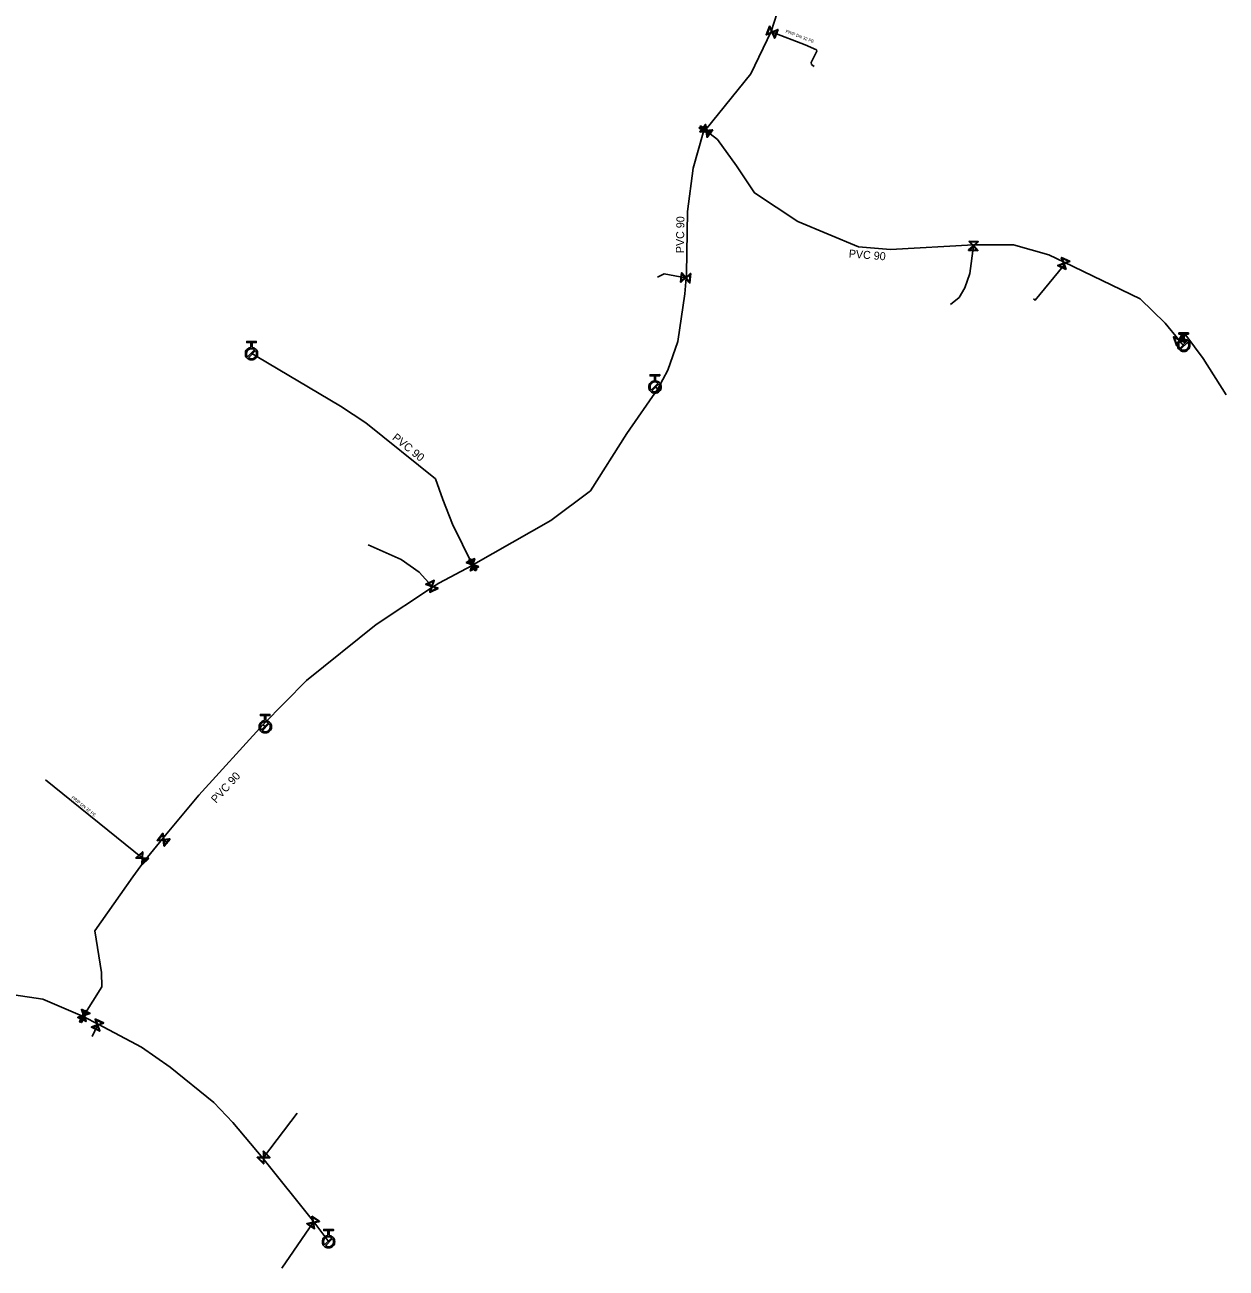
# Model space of a CAD drawing. Extents: x -641905 to -641246, y -1111750 to -1110210.
# Drawn here: x -641516.8 to -641321.7, y -1110794 to -1110592 of the extents above; entities that cross this region are included whole.
import ezdxf

# ---------------------------------------------------------------- set-up
doc = ezdxf.new("R2010")
doc.units = 0
for name, color, linetype in [('Default', 7, 'Continuous'), ('VP Hydrant', 7, 'Continuous'), ('VP Popis přípojky', 7, 'Continuous'), ('VP Přípojka', 7, 'Continuous'), ('VP Řad', 7, 'Continuous'), ('VP Řad - popis', 7, 'Continuous'), ('VP Šoupě', 7, 'Continuous')]:
    doc.layers.add(name, color=color, linetype=linetype)

msp = doc.modelspace()

# ---------------------------------------------------------------- linework, layer by layer
at = {"layer": 'Default'}
for points in [[(-641479.89, -1110644.41), (-641479.53, -1110644.44), (-641479.27, -1110644.7), (-641478.98, -1110645), (-641478.98, -1110645.41), (-641478.98, -1110645.83), (-641479.27, -1110646.12), (-641479.57, -1110646.41), (-641479.98, -1110646.41), (-641480.4, -1110646.41), (-641480.69, -1110646.12), (-641480.98, -1110645.82), (-641480.98, -1110645.41), (-641480.98, -1110644.99), (-641480.69, -1110644.7), (-641480.43, -1110644.44), (-641480.07, -1110644.41)], [(-641328.51, -1110643.03), (-641328.15, -1110643.06), (-641327.89, -1110643.32), (-641327.6, -1110643.61), (-641327.6, -1110644.03), (-641327.6, -1110644.44), (-641327.89, -1110644.74), (-641328.18, -1110645.03), (-641328.6, -1110645.03), (-641329.01, -1110645.03), (-641329.3, -1110644.74), (-641329.6, -1110644.45), (-641329.6, -1110644.04), (-641329.6, -1110643.62), (-641329.31, -1110643.33), (-641329.05, -1110643.06), (-641328.7, -1110643.03)], [(-641328.09, -1110643.39), (-641328.31, -1110643.21), (-641328.6, -1110643.22), (-641328.94, -1110643.22), (-641329.18, -1110643.46), (-641329.42, -1110643.69), (-641329.41, -1110644.03), (-641329.41, -1110644.32), (-641329.23, -1110644.54)], [(-641329.11, -1110644.67), (-641328.89, -1110644.84), (-641328.6, -1110644.84), (-641328.26, -1110644.84), (-641328.03, -1110644.6), (-641327.79, -1110644.36), (-641327.79, -1110644.03), (-641327.79, -1110643.74), (-641327.96, -1110643.52)], [(-641479.47, -1110644.77), (-641479.69, -1110644.6), (-641479.98, -1110644.6), (-641480.32, -1110644.6), (-641480.56, -1110644.83), (-641480.79, -1110645.07), (-641480.79, -1110645.41), (-641480.79, -1110645.7), (-641480.62, -1110645.92)], [(-641480.49, -1110646.05), (-641480.27, -1110646.22), (-641479.98, -1110646.22), (-641479.65, -1110646.22), (-641479.41, -1110645.98), (-641479.17, -1110645.75), (-641479.17, -1110645.41), (-641479.17, -1110645.12), (-641479.34, -1110644.9)], [(-641414.37, -1110649.81), (-641414.01, -1110649.84), (-641413.75, -1110650.09), (-641413.46, -1110650.39), (-641413.45, -1110650.8), (-641413.45, -1110651.22), (-641413.74, -1110651.51), (-641414.03, -1110651.8), (-641414.45, -1110651.81), (-641414.86, -1110651.81), (-641415.15, -1110651.52), (-641415.45, -1110651.23), (-641415.45, -1110650.82), (-641415.46, -1110650.4), (-641415.17, -1110650.11), (-641414.91, -1110649.84), (-641414.55, -1110649.81)], [(-641413.95, -1110650.17), (-641414.17, -1110649.99), (-641414.46, -1110649.99), (-641414.8, -1110649.99), (-641415.03, -1110650.23), (-641415.27, -1110650.47), (-641415.27, -1110650.81), (-641415.26, -1110651.1), (-641415.09, -1110651.32)], [(-641414.96, -1110651.45), (-641414.74, -1110651.62), (-641414.45, -1110651.62), (-641414.11, -1110651.61), (-641413.88, -1110651.38), (-641413.64, -1110651.14), (-641413.64, -1110650.8), (-641413.64, -1110650.51), (-641413.82, -1110650.29)], [(-641477.66, -1110705.01), (-641477.3, -1110705.04), (-641477.04, -1110705.3), (-641476.75, -1110705.59), (-641476.75, -1110706.01), (-641476.75, -1110706.42), (-641477.04, -1110706.71), (-641477.33, -1110707.01), (-641477.75, -1110707.01), (-641478.16, -1110707.01), (-641478.45, -1110706.72), (-641478.75, -1110706.43), (-641478.75, -1110706.02), (-641478.75, -1110705.6), (-641478.46, -1110705.31), (-641478.21, -1110705.04), (-641477.85, -1110705.01)], [(-641477.24, -1110705.37), (-641477.46, -1110705.19), (-641477.76, -1110705.2), (-641478.09, -1110705.2), (-641478.33, -1110705.44), (-641478.57, -1110705.67), (-641478.56, -1110706.01), (-641478.56, -1110706.3), (-641478.38, -1110706.52)], [(-641478.25, -1110706.65), (-641478.04, -1110706.82), (-641477.75, -1110706.82), (-641477.41, -1110706.82), (-641477.17, -1110706.58), (-641476.94, -1110706.34), (-641476.94, -1110706), (-641476.94, -1110705.71), (-641477.12, -1110705.5)], [(-641467.38, -1110788.67), (-641467.02, -1110788.7), (-641466.76, -1110788.96), (-641466.47, -1110789.26), (-641466.47, -1110789.67), (-641466.47, -1110790.09), (-641466.76, -1110790.38), (-641467.06, -1110790.67), (-641467.47, -1110790.67), (-641467.89, -1110790.67), (-641468.18, -1110790.38), (-641468.47, -1110790.08), (-641468.47, -1110789.67), (-641468.47, -1110789.25), (-641468.18, -1110788.96), (-641467.92, -1110788.7), (-641467.56, -1110788.67)], [(-641466.96, -1110789.03), (-641467.18, -1110788.86), (-641467.47, -1110788.86), (-641467.81, -1110788.86), (-641468.05, -1110789.09), (-641468.28, -1110789.33), (-641468.28, -1110789.67), (-641468.28, -1110789.96), (-641468.11, -1110790.18)], [(-641467.98, -1110790.31), (-641467.76, -1110790.48), (-641467.47, -1110790.48), (-641467.14, -1110790.48), (-641466.9, -1110790.24), (-641466.66, -1110790.01), (-641466.66, -1110789.67), (-641466.66, -1110789.38), (-641466.83, -1110789.16)]]:
    msp.add_open_spline(points, degree=3, dxfattribs=at)
at = {"layer": 'VP Hydrant'}
for points in [[(-641328.7, -1110643.03), (-641328.7, -1110642.21), (-641329.39, -1110642.22), (-641329.39, -1110642.03), (-641327.83, -1110642.03), (-641327.83, -1110642.21), (-641328.51, -1110642.21), (-641328.51, -1110643.03)], [(-641480.07, -1110644.41), (-641480.07, -1110643.59), (-641480.76, -1110643.59), (-641480.76, -1110643.41), (-641479.2, -1110643.41), (-641479.2, -1110643.6), (-641479.89, -1110643.59), (-641479.89, -1110644.41)], [(-641329.23, -1110644.54), (-641328.09, -1110643.39)], [(-641327.96, -1110643.52), (-641329.11, -1110644.67)], [(-641480.62, -1110645.92), (-641479.47, -1110644.77)], [(-641479.34, -1110644.9), (-641480.49, -1110646.05)], [(-641414.55, -1110649.81), (-641414.56, -1110648.99), (-641415.25, -1110649), (-641415.25, -1110648.81), (-641413.69, -1110648.8), (-641413.68, -1110648.98), (-641414.37, -1110648.99), (-641414.37, -1110649.81)], [(-641415.09, -1110651.32), (-641413.95, -1110650.17)], [(-641413.82, -1110650.29), (-641414.96, -1110651.45)], [(-641477.85, -1110705.01), (-641477.85, -1110704.19), (-641478.54, -1110704.2), (-641478.54, -1110704.01), (-641476.98, -1110704.01), (-641476.98, -1110704.19), (-641477.67, -1110704.19), (-641477.66, -1110705.01)], [(-641478.38, -1110706.52), (-641477.24, -1110705.37)], [(-641477.12, -1110705.5), (-641478.25, -1110706.65)], [(-641467.56, -1110788.67), (-641467.56, -1110787.85), (-641468.25, -1110787.85), (-641468.25, -1110787.67), (-641466.68, -1110787.67), (-641466.68, -1110787.86), (-641467.37, -1110787.85), (-641467.38, -1110788.67)], [(-641468.11, -1110790.18), (-641466.96, -1110789.03)], [(-641466.83, -1110789.16), (-641467.98, -1110790.31)]]:
    msp.add_lwpolyline(points, dxfattribs=at)
at = {"layer": 'VP Přípojka'}
for points in [[(-641395.57, -1110593.08), (-641395.44, -1110593.17), (-641390.05, -1110595.24), (-641388.26, -1110596.06), (-641388.18, -1110596.27), (-641389.1, -1110598.1), (-641389.05, -1110598.41), (-641388.63, -1110598.73)], [(-641362.75, -1110627.69), (-641362.76, -1110627.9), (-641363.32, -1110632.37), (-641364.13, -1110634.68), (-641365.05, -1110636.27), (-641366.49, -1110637.4)], [(-641348, -1110630.55), (-641348.09, -1110630.75), (-641348.19, -1110631.16), (-641352.74, -1110636.71), (-641352.98, -1110636.48)], [(-641409.38, -1110633.09), (-641409.48, -1110633.08), (-641412.98, -1110632.43), (-641414.06, -1110632.98)], [(-641329.42, -1110643.17), (-641329.31, -1110643.13), (-641328.24, -1110642.4), (-641325.44, -1110646.17), (-641321.72, -1110652.11)], [(-641329.42, -1110643.17), (-641328.93, -1110643.78), (-641328.6, -1110644.03)], [(-641479.14, -1110645.84), (-641479.19, -1110645.93), (-641479.75, -1110646.36)], [(-641479.3, -1110645.75), (-641479.26, -1110645.69)], [(-641414.01, -1110651.09), (-641414.2, -1110650.97), (-641414.46, -1110650.8)], [(-641450.6, -1110683.34), (-641450.68, -1110683.18), (-641452.75, -1110680.91), (-641455.69, -1110678.84), (-641461.01, -1110676.46)], [(-641478.07, -1110705.66), (-641477.92, -1110705.86), (-641477.75, -1110706.01)], [(-641497.33, -1110727.77), (-641497.7, -1110727.36), (-641513.43, -1110714.64)], [(-641494.45, -1110724.21), (-641493.57, -1110724.89)], [(-641504.9, -1110754.3), (-641504.98, -1110754.47), (-641505.87, -1110756.34)], [(-641478.12, -1110776.08), (-641478.01, -1110775.97), (-641472.56, -1110768.8)], [(-641475.05, -1110793.95), (-641469.97, -1110786.54), (-641469.86, -1110786.42)], [(-641467.56, -1110789.47), (-641467.47, -1110789.67)]]:
    msp.add_lwpolyline(points, dxfattribs=at)
at = {"layer": 'VP Řad'}
for points in [[(-641406.62, -1110609.5), (-641406.42, -1110609.23), (-641406.35, -1110609.14), (-641406.3, -1110609.07), (-641406.23, -1110608.97), (-641398.89, -1110599.95), (-641395.57, -1110593.08), (-641393.64, -1110586.94), (-641393.63, -1110586.92), (-641392.58, -1110582.16), (-641391.51, -1110573.9), (-641391.83, -1110571.17), (-641393.23, -1110561.05), (-641393.28, -1110556.19), (-641394.73, -1110550.07), (-641395.83, -1110545.45), (-641395.85, -1110545.41), (-641395.9, -1110545.32), (-641397.5, -1110542.1), (-641404.8, -1110534.12), (-641410.42, -1110529.73), (-641417.1, -1110526.46)], [(-641444.03, -1110679.73), (-641443.93, -1110679.67), (-641431.4, -1110672.52), (-641424.94, -1110667.67), (-641419.04, -1110658.36), (-641414.01, -1110651.09), (-641412.35, -1110648.05), (-641410.74, -1110643.43), (-641409.63, -1110635.65), (-641409.38, -1110633.09), (-641409.32, -1110632.45), (-641409.16, -1110622.32), (-641408.25, -1110615.26), (-641406.62, -1110609.5)], [(-641406.3, -1110609.07), (-641406.23, -1110609.15), (-641404.29, -1110610.63), (-641401.21, -1110614.86), (-641398.29, -1110619.27), (-641391.25, -1110623.94), (-641381.4, -1110628.05), (-641376.23, -1110628.47), (-641362.75, -1110627.69), (-641356.26, -1110627.74), (-641350.48, -1110629.35), (-641348, -1110630.55), (-641335.7, -1110636.49), (-641331.6, -1110640.43), (-641329.42, -1110643.17)], [(-641479.14, -1110645.84), (-641479.3, -1110645.75), (-641479.63, -1110645.55), (-641479.98, -1110645.41)], [(-641444.03, -1110679.73), (-641444.09, -1110679.68), (-641444.09, -1110679.68), (-641447.35, -1110673.1), (-641448.91, -1110669.07), (-641450.11, -1110665.73), (-641461.39, -1110656.64), (-641465.55, -1110653.94), (-641479.14, -1110645.84)], [(-641507.31, -1110753.07), (-641507.2, -1110752.9), (-641504.29, -1110748.23), (-641504.36, -1110745.91), (-641505.4, -1110739.15), (-641499.25, -1110730.39), (-641498.4, -1110729.18), (-641497.33, -1110727.77), (-641494.45, -1110724.21), (-641493.95, -1110723.59), (-641488.51, -1110717.1), (-641478.07, -1110705.66), (-641471.04, -1110698.49), (-641459.74, -1110689.42), (-641450.6, -1110683.34), (-641449.55, -1110682.68), (-641444.16, -1110679.81), (-641444.03, -1110679.73)], [(-641624.02, -1110725.37), (-641622.04, -1110726.09), (-641605.04, -1110732.39), (-641592.38, -1110736.75), (-641580.95, -1110740.68), (-641580.55, -1110740.8), (-641577.05, -1110741.87), (-641571.34, -1110743.62), (-641560.51, -1110747.22), (-641550.89, -1110749.28), (-641542.88, -1110749.95), (-641530.96, -1110748.44), (-641525.88, -1110748.46), (-641513.84, -1110750.25), (-641507.42, -1110753.04), (-641507.31, -1110753.07)], [(-641507.31, -1110753.07), (-641507.19, -1110753.15), (-641504.9, -1110754.3), (-641497.86, -1110758.07), (-641493.16, -1110761.28), (-641486.08, -1110767.06), (-641483, -1110770.28), (-641478.12, -1110776.08), (-641469.86, -1110786.42), (-641467.56, -1110789.47)]]:
    msp.add_lwpolyline(points, dxfattribs=at)
at = {"layer": 'VP Šoupě'}
for points in [[(-641394.47, -1110592.75), (-641395.02, -1110594.14), (-641395.08, -1110594.12), (-641395.13, -1110594), (-641395.46, -1110593.23), (-641396.35, -1110593.61), (-641396.41, -1110593.59), (-641395.86, -1110592.2), (-641395.8, -1110592.22), (-641395.42, -1110593.11), (-641394.64, -1110592.78), (-641394.53, -1110592.73), (-641394.47, -1110592.75)], [(-641396.27, -1110593.48), (-641395.5, -1110593.15), (-641395.83, -1110592.38), (-641396.27, -1110593.48)], [(-641394.61, -1110592.86), (-641395.38, -1110593.19), (-641395.05, -1110593.96), (-641394.61, -1110592.86)], [(-641405.6, -1110609.81), (-641407.3, -1110608.75), (-641407.23, -1110608.64), (-641405.53, -1110609.7), (-641405.6, -1110609.81)], [(-641405.07, -1110609.06), (-641405.98, -1110610.26), (-641406.04, -1110610.22), (-641406.05, -1110610.09), (-641406.16, -1110609.26), (-641407.12, -1110609.39), (-641407.18, -1110609.35), (-641406.27, -1110608.15), (-641406.21, -1110608.19), (-641406.09, -1110609.16), (-641405.25, -1110609.04), (-641405.13, -1110609.02), (-641405.07, -1110609.06)], [(-641405.41, -1110609.54), (-641407.12, -1110608.51), (-641407.05, -1110608.4), (-641405.34, -1110609.43), (-641405.41, -1110609.54)], [(-641407.01, -1110609.28), (-641406.17, -1110609.17), (-641406.29, -1110608.33), (-641407.01, -1110609.28)], [(-641405.24, -1110609.13), (-641406.07, -1110609.24), (-641405.96, -1110610.07), (-641405.24, -1110609.13)], [(-641363.47, -1110627.12), (-641361.98, -1110627.19), (-641361.98, -1110627.25), (-641362.08, -1110627.34), (-641362.7, -1110627.9), (-641362.04, -1110628.62), (-641362.05, -1110628.69), (-641363.54, -1110628.61), (-641363.54, -1110628.55), (-641362.82, -1110627.9), (-641363.39, -1110627.28), (-641363.48, -1110627.18), (-641363.47, -1110627.12)], [(-641362.19, -1110628.58), (-641362.76, -1110627.96), (-641363.38, -1110628.53), (-641362.19, -1110628.58)], [(-641363.32, -1110627.22), (-641362.76, -1110627.84), (-641362.14, -1110627.27), (-641363.32, -1110627.22)], [(-641347.74, -1110631.74), (-641349.09, -1110631.1), (-641349.06, -1110631.04), (-641348.94, -1110631), (-641348.15, -1110630.72), (-641348.48, -1110629.81), (-641348.45, -1110629.75), (-641347.09, -1110630.39), (-641347.12, -1110630.45), (-641348.04, -1110630.77), (-641347.75, -1110631.56), (-641347.71, -1110631.69), (-641347.74, -1110631.74)], [(-641348.35, -1110629.9), (-641348.07, -1110630.69), (-641347.27, -1110630.41), (-641348.35, -1110629.9)], [(-641408.66, -1110632.4), (-641408.8, -1110633.9), (-641408.87, -1110633.89), (-641408.95, -1110633.79), (-641409.48, -1110633.14), (-641410.23, -1110633.76), (-641410.3, -1110633.76), (-641410.16, -1110632.27), (-641410.09, -1110632.27), (-641409.47, -1110633.02), (-641408.83, -1110632.48), (-641408.73, -1110632.4), (-641408.66, -1110632.4)], [(-641347.84, -1110631.59), (-641348.12, -1110630.8), (-641348.91, -1110631.09), (-641347.84, -1110631.59)], [(-641410.19, -1110633.62), (-641409.54, -1110633.08), (-641410.08, -1110632.43), (-641410.19, -1110633.62)], [(-641408.77, -1110632.55), (-641409.42, -1110633.09), (-641408.88, -1110633.73), (-641408.77, -1110632.55)], [(-641328.86, -1110642.17), (-641328.35, -1110643.58), (-641328.41, -1110643.6), (-641328.53, -1110643.54), (-641329.29, -1110643.19), (-641329.7, -1110644.07), (-641329.76, -1110644.09), (-641330.27, -1110642.68), (-641330.21, -1110642.66), (-641329.33, -1110643.07), (-641328.98, -1110642.31), (-641328.92, -1110642.19), (-641328.86, -1110642.17)], [(-641328.9, -1110642.35), (-641329.25, -1110643.11), (-641328.49, -1110643.46), (-641328.9, -1110642.35)], [(-641329.72, -1110643.92), (-641329.37, -1110643.15), (-641330.13, -1110642.8), (-641329.72, -1110643.92)], [(-641443.09, -1110680.02), (-641444.43, -1110680.69), (-641444.46, -1110680.63), (-641444.42, -1110680.51), (-641444.15, -1110679.71), (-641445.07, -1110679.4), (-641445.1, -1110679.34), (-641443.76, -1110678.68), (-641443.73, -1110678.74), (-641444.04, -1110679.66), (-641443.24, -1110679.92), (-641443.12, -1110679.96), (-641443.09, -1110680.02)], [(-641443.5, -1110680.57), (-641444.47, -1110678.83), (-641444.36, -1110678.77), (-641443.39, -1110680.51), (-641443.5, -1110680.57)], [(-641444.92, -1110679.36), (-641444.12, -1110679.63), (-641443.85, -1110678.83), (-641444.92, -1110679.36)], [(-641443.68, -1110680.69), (-641444.75, -1110679), (-641444.64, -1110678.93), (-641443.57, -1110680.62), (-641443.68, -1110680.69)], [(-641443.27, -1110680.01), (-641444.07, -1110679.74), (-641444.33, -1110680.53), (-641443.27, -1110680.01)], [(-641449.67, -1110683.52), (-641451.01, -1110684.19), (-641451.04, -1110684.13), (-641451, -1110684.01), (-641450.74, -1110683.21), (-641451.66, -1110682.9), (-641451.69, -1110682.84), (-641450.34, -1110682.17), (-641450.31, -1110682.23), (-641450.62, -1110683.15), (-641449.83, -1110683.42), (-641449.7, -1110683.46), (-641449.67, -1110683.52)], [(-641451.51, -1110682.86), (-641450.71, -1110683.13), (-641450.44, -1110682.33), (-641451.51, -1110682.86)], [(-641449.86, -1110683.5), (-641450.65, -1110683.24), (-641450.92, -1110684.03), (-641449.86, -1110683.5)], [(-641493.21, -1110724.24), (-641494.14, -1110725.41), (-641494.19, -1110725.37), (-641494.2, -1110725.25), (-641494.3, -1110724.41), (-641495.26, -1110724.52), (-641495.31, -1110724.48), (-641494.38, -1110723.31), (-641494.33, -1110723.35), (-641494.22, -1110724.31), (-641493.39, -1110724.22), (-641493.26, -1110724.2), (-641493.21, -1110724.24)], [(-641495.15, -1110724.42), (-641494.31, -1110724.32), (-641494.4, -1110723.49), (-641495.15, -1110724.42)], [(-641493.38, -1110724.31), (-641494.21, -1110724.4), (-641494.12, -1110725.23), (-641493.38, -1110724.31)], [(-641496.65, -1110727.4), (-641497.75, -1110728.42), (-641497.79, -1110728.37), (-641497.78, -1110728.24), (-641497.75, -1110727.4), (-641498.72, -1110727.36), (-641498.77, -1110727.32), (-641497.66, -1110726.3), (-641497.62, -1110726.35), (-641497.66, -1110727.32), (-641496.82, -1110727.35), (-641496.69, -1110727.35), (-641496.65, -1110727.4)], [(-641498.59, -1110727.28), (-641497.75, -1110727.31), (-641497.72, -1110726.47), (-641498.59, -1110727.28)], [(-641496.82, -1110727.44), (-641497.66, -1110727.4), (-641497.69, -1110728.24), (-641496.82, -1110727.44)], [(-641507.57, -1110751.9), (-641506.21, -1110752.53), (-641506.23, -1110752.59), (-641506.36, -1110752.63), (-641507.14, -1110752.92), (-641506.81, -1110753.83), (-641506.84, -1110753.89), (-641508.2, -1110753.26), (-641508.17, -1110753.2), (-641507.26, -1110752.87), (-641507.55, -1110752.08), (-641507.59, -1110751.96), (-641507.57, -1110751.9)], [(-641506.94, -1110753.74), (-641507.23, -1110752.95), (-641508.02, -1110753.24), (-641506.94, -1110753.74)], [(-641506.94, -1110752.16), (-641507.79, -1110753.97), (-641507.9, -1110753.92), (-641507.05, -1110752.11), (-641506.94, -1110752.16)], [(-641506.66, -1110752.3), (-641507.61, -1110754.06), (-641507.72, -1110754), (-641506.77, -1110752.24), (-641506.66, -1110752.3)], [(-641507.46, -1110752.05), (-641507.17, -1110752.84), (-641506.39, -1110752.55), (-641507.46, -1110752.05)], [(-641505.34, -1110753.47), (-641503.98, -1110754.11), (-641504.01, -1110754.17), (-641504.13, -1110754.21), (-641504.92, -1110754.5), (-641504.59, -1110755.41), (-641504.62, -1110755.47), (-641505.98, -1110754.83), (-641505.95, -1110754.77), (-641505.03, -1110754.44), (-641505.32, -1110753.65), (-641505.37, -1110753.53), (-641505.34, -1110753.47)], [(-641504.72, -1110755.32), (-641505, -1110754.53), (-641505.8, -1110754.81), (-641504.72, -1110755.32)], [(-641505.24, -1110753.62), (-641504.95, -1110754.41), (-641504.16, -1110754.13), (-641505.24, -1110753.62)], [(-641478.01, -1110774.91), (-641476.95, -1110775.97), (-641477, -1110776.02), (-641477.12, -1110776.01), (-641477.96, -1110776.01), (-641477.96, -1110776.98), (-641478.01, -1110777.03), (-641479.07, -1110775.97), (-641479.02, -1110775.92), (-641478.05, -1110775.93), (-641478.05, -1110775.09), (-641478.06, -1110774.96), (-641478.01, -1110774.91)], [(-641477.96, -1110775.09), (-641477.96, -1110775.93), (-641477.13, -1110775.92), (-641477.96, -1110775.09)], [(-641478.05, -1110776.86), (-641478.05, -1110776.01), (-641478.89, -1110776.01), (-641478.05, -1110776.86)], [(-641470.16, -1110785.5), (-641468.93, -1110786.34), (-641468.96, -1110786.4), (-641469.09, -1110786.42), (-641469.92, -1110786.57), (-641469.74, -1110787.53), (-641469.77, -1110787.58), (-641471.01, -1110786.73), (-641470.98, -1110786.68), (-641470.02, -1110786.5), (-641470.18, -1110785.68), (-641470.2, -1110785.55), (-641470.16, -1110785.5)], [(-641470.09, -1110785.66), (-641469.93, -1110786.49), (-641469.11, -1110786.33), (-641470.09, -1110785.66)], [(-641469.85, -1110787.42), (-641470, -1110786.59), (-641470.83, -1110786.75), (-641469.85, -1110787.42)]]:
    msp.add_lwpolyline(points, dxfattribs=at)

# ---------------------------------------------------------------- texts
at = {"layer": 'VP Popis přípojky'}
for rotation, p in [(338.991, (-641393.3, -1110593.21)), (321.0211, (-641509.27, -1110717.58))]:
    msp.add_text('PRIP DN 32 PE', height=0.5, rotation=rotation, dxfattribs=at).set_placement(p)
at = {"layer": 'VP Řad - popis'}
for rotation, p in [(89.0951, (-641409.77, -1110629.08)), (355.3556, (-641383.03, -1110629.76)), (321.1364, (-641457.23, -1110659.24)), (47.6168, (-641485.73, -1110718.51))]:
    msp.add_text('PVC 90', height=1.3, rotation=rotation, dxfattribs=at).set_placement(p)

doc.saveas('drawing.dxf')
